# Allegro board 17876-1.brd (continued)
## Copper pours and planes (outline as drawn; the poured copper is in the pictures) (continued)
GND on BOTTOM: 66.36,27.43 65.09,28.7 65.09,34.81 65.3,35.03 66.29,35.03 66.52,34.8 70.98,34.8 72.89,32.89 72.89,31.26 73.75,30.39 73.75,27.84 73.72,27.81 71.41,27.81 71.03,27.43 ; 3 cut-outs
GND on BOTTOM: 19.81,75.62 18.75,76.68 18.14,76.68 17.93,76.89 17.93,78.21 18.75,79.03 18.76,79.02 21.54,79.02 21.72,78.84 21.72,75.8 21.54,75.62 ; 2 cut-outs
GND on BOTTOM: 72.03,39.93 71.77,40.18 71.63,40.18 71.55,40.26 71.55,40.54 72,40.99 72,41.62 72.15,41.78 72.4,41.78 72.61,41.56 74.16,41.56 74.27,41.68 74.27,42.13 74.07,42.33 73.86,42.33 73.52,42.67 73.19,42.67 72.44,43.43 72.44,45 72.46,45.02 72.88,45.02 73.02,44.88 73.02,44.68 74.39,43.32 74.59,43.32 75.2,42.71 75.2,42.65 74.73,42.17 74.73,41.73 75.51,40.95 75.83,40.95 75.93,40.84 76.33,40.84 76.43,40.95 76.83,40.95 76.94,40.84 77.14,40.84 77.24,40.95 77.98,40.95 78.11,40.82 79.55,40.82 79.58,40.84 79.58,41.43 79.15,41.86 79.15,41.96 79.32,42.14 79.38,42.14 80.31,43.08 80.31,43.28 79.73,43.87 79.73,44.12 79.86,44.25 80.14,44.25 80.7,43.69 80.7,42.57 80.14,42.01 80.14,41.86 80.29,41.71 80.29,40.92 80.42,40.79 81.74,40.79 82.02,41.07 82.37,41.07 82.85,40.59 82.85,40.29 82.83,40.26 79.2,40.26 79.07,40.39 78.64,40.39 78.54,40.29 78.13,40.29 78.03,40.39 77.47,40.39 77.33,40.25 75.74,40.25 75.66,40.33 73.25,40.33 72.91,39.99 72.56,39.99 72.5,39.93
GND on BOTTOM: 98.7,90.32 97.61,91.42 97.61,92.58 97.92,92.89 101.85,92.89 102.13,92.61 102.13,90.65 101.8,90.32 ; 4 cut-outs
GND on L2VCC: outline of 118 points within 0.51,0.51 178.39,102.49 ; 2 cut-outs
GND on L3: outline of 131 points within 0.51,0.51 178.39,102.49 ; 2 cut-outs
GND on L4: outline of 126 points within 0.51,0.51 178.39,102.49 ; 2 cut-outs
GND on L5GND: outline of 118 points within 0.51,0.51 178.39,102.49 ; 1 cut-out
VDDCR_FCH on TOP: 68.76,57.66 68.71,57.71 68.71,59.49 66.85,59.49 65.99,60.35 64.92,60.35 64.67,60.1 64.01,60.1 63.8,59.89 62.76,59.89 62.64,60.02 61.21,60.02 59.94,61.29 59.94,62.69 59.95,62.69 59.95,63.18 60.15,63.38 66.39,63.38 69.06,60.71 70.38,60.71 70.9,60.19 71.64,60.19 71.78,60.05 71.78,58.88 71.2,58.29 70.31,58.29 69.67,57.66
VDDCR_FCH on BOTTOM: 60.81,60.45 60.6,60.66 60.1,60.66 59.39,61.37 59.39,66.24 59.49,66.35 60.3,66.35 60.83,65.81 60.83,62.21 61.47,61.57 61.47,60.58 61.34,60.45 ; 4 cut-outs
VDDCR_FCH on BOTTOM: 70.11,57.74 69.86,57.99 69.86,58.37 70.49,59.01 71.76,59.01 72.02,58.76 72.02,58.37 72.14,58.25 72.14,57.87 72.02,57.74
VDDCR_FCH on L3: 71.81,60.17 71.81,58.57 71.53,58.29 70.28,58.29 70.18,58.4 70.18,58.85 70.04,58.99 66.76,58.99 65.56,60.2 64.95,60.2 64.68,59.93 63.86,59.93 63.67,59.74 61.24,59.74 60.1,60.89 60.1,62.56 60.63,63.1 61.52,63.1 62.1,62.51 63.86,62.51 64.97,61.39 70.59,61.39
0D6V_VREF_S0 on BOTTOM: 131.65,85.14 131.27,85.52 131.27,86.06 131.06,86.26 129.26,86.26 129.24,86.29 129.24,86.46 129.29,86.51 131.11,86.51 131.37,86.77 131.37,87 131.44,87.07 132.77,87.07 132.92,86.92 132.92,86.06 132,85.14 ; 1 cut-out
0D6V_VREF_S0 on BOTTOM: 140.21,38.99 140.13,39.07 140.13,40.36 140.23,40.46 141.66,40.46 141.78,40.34 141.78,39.14 141.63,38.99
0D95V_S0 on TOP: 41.78,90.12 41.66,90.25 41.66,90.88 41.78,91.01 42.93,91.01 43.31,91.39 43.56,91.39 43.69,91.26 43.69,90.76 43.05,90.12
0D95V_S0 on TOP: 80.79,53.6 80.62,53.77 80.62,55.63 80.44,55.63 80.26,55.81 80.26,57.15 79.68,57.74 79.68,59.46 79.38,59.77 79.38,61.6 79.6,61.83 79.6,63.45 79.15,63.91 79.15,64.59 78.33,65.41 78.33,66.68 74.4,70.61 74.4,78.74 74.52,78.87 75.16,78.87 75.92,79.63 77.24,79.63 77.69,79.19 77.69,78.55 79.15,77.09 81.51,77.09 84.87,73.73 84.87,60.09 85.12,59.84 85.12,57.84 85.39,57.56 85.39,56.11 84.73,55.45 84.73,54.66 84.68,54.61 82.51,54.61 82,54.1 81.53,54.1 81.03,53.6 ; 17 cut-outs
0D95V_S0 on BOTTOM: 75.78,75.81 75.62,75.97 75.62,79.81 75.59,79.83 77.11,79.83 77.44,79.5 78.51,79.5 78.56,79.45 78.56,76.63 77.74,75.81 ; 3 cut-outs
0D95V_S0 on BOTTOM: 80.72,53.46 80.08,54.09 79.25,54.09 79.13,54.22 79.13,54.56 79.73,55.17 79.73,55.52 79.63,55.63 79.63,56.72 79.65,56.74 79.65,58.69 80.19,59.23 81.8,59.23 82.48,58.55 82.48,58.19 81.6,57.3 81.6,56.57 81.69,56.48 82.33,56.48 82.83,55.98 83.38,55.98 83.57,55.79 83.57,54.91 83.06,54.4 83.04,54.4 83.04,54.17 82.84,53.97 82.14,53.97 81.99,54.12 81.67,54.12 81.01,53.46
0D95V_S0 on L2VCC: 84.34,56.24 84.34,51.87 83.94,51.47 79.67,51.47 79.41,51.74 79.41,52.48 78.54,53.36 78.54,74.21 76.6,76.15 76.6,79.77 78.27,81.44 78.27,82.68 77.65,83.31 64.72,83.31 60.81,79.39 57.74,79.39 56.85,80.28 54.69,80.28 52.91,82.06 48.21,82.06 43.62,86.64 43.62,89.44 43,90.06 41.73,90.06 41.59,90.2 41.59,90.93 41.73,91.07 42.88,91.07 43.26,91.45 43.48,91.45 44.64,90.3 44.64,87.11 48.62,83.13 53.34,83.13 54.6,81.86 59.49,81.86 59.92,82.29 60.63,82.29 62.8,84.45 78.47,84.45 86.83,76.09 86.83,65.92 86.31,65.39 86.31,60.47 85.84,60 85.84,58.27 86.11,58.01
0D95V_S0 on L3: 82.64,51.41 79.98,51.41 79.38,52.01 79.38,52.99 78.59,53.79 78.59,54.1 80.77,56.29 80.77,58.52 80.95,58.7 82.19,58.7 82.4,58.5 82.4,57.15 82.62,56.93 83.03,56.93 84.26,55.7 84.26,53.03
0D95V_S0 on L4: 79.71,64.82 80.29,64.24 81.15,64.24 81.38,64.01 81.38,63.25 83.24,61.39 84.48,61.39 85.14,60.73 85.14,55.58 82.68,53.11 79.55,53.11 79.3,53.37 79.3,59.16 79.38,59.23 79.38,60.17 78.23,61.32 78.23,64.19 78.83,64.78 78.83,65.37 79.1,65.64 79.35,65.64 79.71,65.28
0D95V_S5 on TOP: 50.42,72.44 50.19,72.67 50.19,76.35 50.32,76.48 51.61,76.48 52.63,75.47 52.63,74.37 52.61,74.36 52.61,73.47 51.59,72.44
0D95V_S5 on TOP: 74.95,52.5 74.88,52.57 74.88,53.34 74.14,54.08 73.57,54.08 73.27,54.38 72.72,54.38 72.64,54.46 72.64,55.04 72.7,55.1 74.97,55.1 75.35,54.71 75.82,54.71 75.93,54.6 75.93,54.15 75.79,54.01 75.61,54.01 75.49,53.89 75.49,52.53 75.46,52.5 ; 1 cut-out
0D95V_S5 on BOTTOM: 74.04,80.01 73.79,80.27 73.79,83.09 74.12,83.42 77.34,83.42 77.8,82.96 78.46,82.96 78.64,82.78 78.64,81.05 78.46,80.88 77.93,80.88 77.74,80.68 77.74,80.43 77.32,80.01
0D95V_S5 on BOTTOM: 50.42,72.44 50.19,72.67 50.19,76.35 50.32,76.48 51.61,76.48 52.63,75.47 52.63,74.37 52.12,73.86 52.12,72.98 51.59,72.44
0D95V_S5 on L2VCC: 78.16,53.73 77.88,53.46 75.09,53.46 74.64,53.9 74.64,65.36 74.21,65.79 74.21,70.51 71.38,73.34 66.22,73.34 64.01,71.13 52.53,71.13 50.61,73.05 50.61,76.2 50.75,76.34 60.68,76.34 61.15,76.81 61.15,79.19 64.88,82.93 77.49,82.93 77.89,82.52 77.89,81.59 76.22,79.92 76.22,75.99 78.16,74.05
0D95V_S5 on L3: 50.55,73.1 51.31,72.34 57.1,72.34 57.35,72.09 59.13,72.09 59.41,72.37 61.29,72.37 66.78,77.85 70.79,77.85 73.91,80.98 75.95,80.98 76.96,81.99 76.96,84.15 76.45,84.66 61.26,84.66 59.45,82.84 56.86,82.84 56.36,82.35 56.36,80.6 57.63,79.33 57.63,78.56 56.95,77.88 55.85,77.88 55.83,77.85 55.47,77.85 54.74,77.12 52.04,77.12 50.55,75.62
1D2V_CPU_VDDNB on TOP: 83.62,51.56 82.97,52.21 82.75,52.21 82.62,52.34 82.62,53.42 82.69,53.49 83.31,53.49 83.52,53.29 83.52,52.88 83.51,52.87 83.51,52.65 83.99,52.17 83.99,51.74 83.81,51.56
1D2V_CPU_VDDNB on TOP: outline of 85 points within 70.51,40.08 81.16,53.36 ; 27 cut-outs
1D2V_CPU_VDDNB on BOTTOM: 47.5,55.83 47.24,56.08 47.24,57.23 47.12,57.35 47.12,60.4 47.62,60.91 47.62,62.05 47.75,62.18 48.82,62.18 49.15,62.51 49.15,63.37 49.61,63.83 53.21,63.83 55.68,66.3 57.33,66.3 57.38,66.24 57.38,65.28 57.15,65.05 57.15,63.04 56.92,62.82 55.45,62.82 54.86,62.23 54.86,56.08 54.61,55.83 ; 6 cut-outs
1D2V_CPU_VDDNB on BOTTOM: outline of 145 points within 71.49,41.18 84.7,53.01
1D2V_CPU_VDDNB on L2VCC: 76.16,43.84 76.16,42.5 75.44,41.77 73.69,41.77 73.21,42.25 64.26,42.25 51.68,54.84 51.68,55.4 51.31,55.77 48.54,55.77 47.71,56.6 47.71,62.14 49.48,62.14 52.86,65.52 73.94,65.52 74.26,65.2 74.26,53.75 74.93,53.08 78.28,53.08 79.03,52.32 79.03,47.55 78.07,46.59 78.07,45.9 77.82,45.66 77.44,45.66 77.13,45.34 77.13,44.81
1D2V_CPU_VDDNB on L3: 78.02,53.41 79.03,52.4 79.03,47.43 78.18,46.59 78.18,45.7 78.03,45.54 77.22,45.54 77.19,45.52 77.19,44.81 76.32,43.94 76.32,42.39 75.61,41.68 73.69,41.68 73.1,42.26 69.31,42.26 69.09,42.04 64.47,42.04 50.81,55.71 50.81,55.71 48.56,55.71 47.8,56.47 47.8,63.02 48.67,63.88 58.72,63.88 58.9,63.7 58.9,61.85 65.71,55.04 65.91,55.04 65.91,54.94 66.92,53.94 68.52,53.94 69.67,52.78 72.47,52.78 73.09,53.41
1D2V_CPU_VDDNB on L4: 83.74,52.96 84.3,52.4 84.3,51.26 84.12,51.08 79.65,51.08 78.99,50.42 78.99,47.37 78.18,46.56 78.18,45.85 77.93,45.59 77.24,45.59 77.19,45.54 77.19,44.83 76.52,44.16 76.19,44.16 75.92,44.43 75.36,44.43 73.18,42.24 71.96,42.24 71.91,42.29 70.92,42.29 70.43,42.78 70.43,45.75 71.37,46.69 71.37,47.17 69.82,48.72 69.82,51.23 71.55,52.96
1D2V_S3 on TOP: 86.73,42.98 86.22,43.48 86.22,44.52 85.61,45.14 85.61,48.1 86.95,49.45 86.95,49.91 86.72,50.14 86.72,50.81 86.85,50.94 86.85,51.72 86.97,51.84 86.97,52.83 86.7,53.1 85.43,53.1 84.73,53.8 84.73,54.43 87.19,54.43 87.29,54.54 87.29,56.23 86.83,56.69 86.74,56.69 86.03,57.41 86.03,59.16 86.2,59.33 87.45,59.33 88.2,60.08 88.2,60.29 88.13,60.36 87.48,60.36 87.4,60.44 87.4,61.55 87.55,61.7 88.06,61.7 88.37,61.39 88.37,61.11 88.52,60.96 93.14,60.96 94.97,59.13 94.97,58.55 95.3,58.22 95.3,53.85 96.98,52.17 96.98,43.56 96.39,42.98 ; 19 cut-outs
1D2V_S3 on TOP: 125.15,45.92 124.26,46.81 123.06,46.81 122.05,47.83 122.05,50.75 122.17,50.88 122.17,55.32 122.68,55.32 122.81,55.45 122.81,56.34 122.68,56.47 122.3,56.47 121.93,56.83 121.93,61.28 121.16,62.05 121.16,62.69 121.28,62.82 127,62.82 127,62.31 127.25,62.05 133.6,62.05 133.73,61.93 133.73,50.29 132.72,49.28 132.72,48.08 131.44,46.81 128.17,46.81 127.28,45.92 ; 28 cut-outs
1D2V_S3 on L2VCC: 123.72,45.48 115.59,37.35 97.81,37.35 96.87,36.41 91.01,36.41 89.6,37.83 89.6,41.08 88.22,42.46 86.54,42.46 86.4,42.6 86.4,44.99 85.69,45.7 85.69,50.4 84.72,51.36 84.72,56.08 86.57,57.93 86.95,57.93 90.38,61.36 92.92,61.36 94.07,62.51 115.46,66.26 125.19,66.26 125.65,65.8 127.03,65.8 127.87,66.64 129.11,66.64 132.35,63.4 132.35,47.93 131.24,46.83 128.17,46.83 126.83,45.48
1D8V_AUX_PWR on BOTTOM: 69.47,21.67 69.19,21.95 68.61,21.95 68.43,22.13 68.43,23.55 68.45,23.57 69.8,23.57 70.23,23.14 70.23,21.72 70.18,21.67 ; 1 cut-out
1D8V_AUX_S5 on TOP: 50.12,23.37 50.01,23.48 50.01,24.29 49.68,24.61 49.68,25.68 49.76,25.76 50.16,25.76 50.27,25.66 50.27,25.22 50.8,24.69 50.8,23.52 50.65,23.37 ; 1 cut-out
1D8V_PWR on BOTTOM: 98.5,93.4 98.4,93.5 98.4,94.44 98.53,94.57 99.47,94.57 99.52,94.62 99.52,99.42 99.57,99.47 100.66,99.47 101.3,98.83 101.3,98.33 102.62,97 102.62,94.72 103.17,94.16 103.17,93.52 103.05,93.4 ; 6 cut-outs
1D8V_PWR_VIN on BOTTOM: 68.53,23.7 68.35,23.88 68.35,25.88 68.36,25.89 68.36,26.18 68.54,26.36 70.02,26.36 70.21,26.17 70.21,23.78 70.13,23.7 ; 3 cut-outs
1D8V_S0 on BOTTOM: 76.86,74.17 76.68,74.35 76.68,75.52 76.76,75.59 77.98,75.59 80.19,77.8 80.19,78.61 79.91,78.89 79.91,79.4 79.98,79.48 81,79.48 81.25,79.73 82.37,79.73 83.08,80.44 83.08,81.03 83.01,81.1 83.01,83.06 83.03,83.06 83.03,84.18 83.16,84.3 83.79,84.3 84.07,84.02 84.07,83.06 84.15,82.98 84.15,79.12 84.12,79.12 83.85,78.84 83.13,78.84 82.5,78.21 82.5,77.17 79.96,74.63 78,74.63 77.55,74.17 ; 4 cut-outs
1D8V_S0 on BOTTOM: 78.26,17.34 78.04,17.57 78.04,18.98 76.56,20.45 76.56,22.16 76.18,22.54 74.46,22.54 74.24,22.77 74.24,25.99 75.48,27.23 78.61,27.23 79.02,26.82 79.53,26.82 79.65,26.95 79.65,27.84 77.8,29.69 77.8,29.71 77.58,29.92 77.58,31.37 77.62,31.41 77.99,31.41 78.08,31.32 86.23,31.32 86.77,30.79 86.77,26.57 87.25,26.09 87.83,26.09 87.99,25.94 87.99,23.95 87.96,23.93 87.53,23.93 87.5,23.95 87.5,24.79 87.35,24.94 86.86,24.94 86.85,24.95 86.3,24.95 85.84,25.41 85.84,26.42 85.39,26.86 85.39,28.5 85.22,28.68 80.95,28.68 80.39,28.12 80.39,26.77 79.83,26.21 79.2,26.21 78.94,26.47 75.72,26.47 75.2,25.95 74.8,25.95 74.59,25.75 74.59,23.15 74.74,23.01 75.35,23.01 75.44,23.09 75.44,23.22 75.42,23.23 75.53,23.34 76.82,23.34 77.4,22.76 77.4,20.96 79.02,19.34 79.02,17.47 78.89,17.34 ; 6 cut-outs
1D8V_S0 on L3: 76.26,68.01 75.91,67.66 75.91,64.26 76.4,63.77 76.4,62.61 76.43,62.59 76.43,61.41 77.38,60.46 77.38,59 76.96,58.58 76.96,56.21 76.48,55.73 76.48,54.98 76.81,54.64 77.46,54.64 77.59,54.77 77.59,55.14 79.48,57.02 79.48,62.66 78.34,63.8 78.34,68.65 78.97,69.29 78.97,70.77 80.07,71.87 80.07,74.21 82.8,76.94 82.8,78.67 82.65,78.82 80.64,78.82 79.25,77.42 79.25,76.79 75.56,73.1 75.56,70.64 76.25,69.95 76.25,68.73 76.26,68.72
1D8V_S5 on TOP: 75.56,55.63 75.49,55.7 75.49,57.1 75.69,57.3 75.69,57.81 76.02,58.14 76.02,59.34 76.05,59.36 76.94,59.36 77.06,59.23 77.06,57.28 76.99,57.2 76.45,57.2 76.3,57.05 76.3,55.78 76.15,55.63 ; 3 cut-outs
1D8V_S5 on BOTTOM: 61.67,32.29 60.86,33.1 59.84,33.1 59.69,33.25 59.69,33.81 59.77,33.89 60.22,33.89 60.4,33.71 61.32,33.71 61.98,33.05 63.3,33.05 63.42,33.17 63.42,33.63 63.55,33.76 64.11,33.76 64.39,34.04 64.74,34.04 64.85,33.94 64.85,33.28 63.86,32.29 ; 2 cut-outs
1D8V_S5 on BOTTOM: 79.98,80.9 79.98,82.07 80.42,82.5 80.42,83.16 80.87,83.62 80.87,87.35 80.62,87.61 80.62,92.71 81.71,93.8 91.31,93.8 91.72,93.4 93.01,93.4 98.17,98.55 99.36,98.55 99.44,98.48 99.44,96.17 99.36,96.09 98.73,96.09 98.42,95.79 98.42,95.4 94.46,91.44 83.21,91.44 82.4,90.63 82.4,90.35 82.68,90.07 82.68,84.76 82.91,84.53 82.91,82.07 81.97,81.13 81.31,81.13 81.29,81.14 81.05,80.9
1D8V_S5 on L3: 76.15,55.58 75.46,55.58 75.3,55.74 75.3,57.24 74.57,57.96 74.57,58.65 73.91,59.31 73.91,59.34 73.36,59.89 73.36,59.92 73.18,60.1 73.18,61.62 72.95,61.85 72.95,71.88 73.19,72.13 73.19,79.62 73.91,80.34 75.44,80.34 75.53,80.43 76.49,80.43 78.49,82.42 78.51,82.42 78.97,82.88 83.59,82.88 85.01,81.46 85.01,80.39 83.83,79.21 79.35,79.21 78.87,78.73 78.87,76.79 74.96,72.87 74.96,69.06 75.64,68.38 75.64,61.72 77.22,60.15 77.22,59.03 76.85,58.66 76.85,58.54 76.83,58.52 76.83,56.26
1D8V_SPI_S5 on BOTTOM: 76.83,25.1 76.73,25.2 76.73,26.29 76.81,26.37 78.87,26.37 79.22,26.01 79.22,25.12 79.2,25.1
1D8V_SPI_S5 on BOTTOM: 79.02,15.06 78.24,15.84 77.61,15.84 77.09,16.36 75.31,16.36 75.18,16.49 75.18,17.17 75.46,17.45 75.46,18.16 75.54,18.24 76.48,18.24 76.82,18.58 76.82,19.28 76.4,19.7 75.23,19.7 74.99,19.93 74.99,20.52 75.41,20.93 75.41,22.26 75.5,22.36 75.92,22.36 76.22,22.06 76.22,20.67 77.89,19 77.89,17.44 78.32,17.01 78.67,17.01 78.67,17.01 78.94,17.01 78.95,17.02 79.04,17.02 79.16,17.14 79.16,17.64 79.33,17.81 79.55,17.81 79.81,17.55 79.81,17.19 79.68,17.07 79.68,15.11 79.63,15.06
3D3V_AUX_KBC on BOTTOM: 71.63,22.96 71.45,23.14 71.45,23.75 71.55,23.85 72.11,23.85 72.31,24.06 72.31,25.2 72.19,25.33 72.19,26.57 72.39,26.77 72.85,26.77 73.09,26.53 73.09,25.8 73.41,25.48 73.41,23.06 73.3,22.96
3D3V_AUX_S5 on TOP: 40.67,22.2 40.54,22.33 40.54,22.94 40.39,23.09 39.7,23.09 39.65,23.14 39.65,23.52 39.78,23.65 41.43,23.65 41.61,23.47 41.61,22.53 41.27,22.2 ; 1 cut-out
3D3V_AUX_S5 on L4: 41.26,22.25 42.8,22.25 43.81,23.27 44.78,23.27 44.88,23.17 46.79,23.17 47.02,23.4 47.02,23.9 46.86,24.06 43.08,24.06 42.24,23.22 41.46,23.22 41.21,22.96 41.2,22.96 41.11,22.87 41.11,22.4
3D3V_CAMERA_S0 on BOTTOM: 68.48,80.32 68.4,80.39 68.4,82.91 68.55,83.06 68.55,83.95 68.12,84.38 67.44,84.38 67.02,84.8 66.66,84.8 66.65,84.81 65.46,84.81 65.46,85.93 65.53,86.01 67.94,86.01 69.67,84.28 69.67,81.79 70.15,81.31 70.15,80.42 70.05,80.32 ; 4 cut-outs
3D3V_CARD on TOP: 15.88,26.62 15.77,26.72 15.77,30.74 15.95,30.91 16.43,30.91 16.61,30.74 16.61,26.67 16.56,26.62
3D3V_CARD on BOTTOM: 6.4,36.78 6.25,36.93 6.25,37.62 6.48,37.85 9.14,37.85 9.3,37.7 10.91,37.7 11.03,37.81 11.03,38.59 11.04,38.59 11.33,38.59 11.34,38.59 11.34,37.73 10.72,37.11 9.86,37.11 9.58,36.83 8.28,36.83 8.23,36.78 ; 3 cut-outs
3D3V_CARD on BOTTOM: 15.93,25.45 15.6,25.78 14.2,25.78 14.17,25.78 14.15,25.8 14.15,26.42 14.17,26.44 15.44,26.44 15.8,26.8 15.8,28.09 16.03,28.32 16.54,28.32 17.18,27.68 17.18,25.52 17.12,25.45 ; 1 cut-out
3D3V_CARD_S0 on BOTTOM: 9.43,35.81 9.35,35.89 9.35,36.5 9.49,36.64 9.63,36.64 9.94,36.96 10.79,36.96 11.56,37.72 11.56,38.61 11.81,38.61 11.86,38.56 11.86,37.31 11.98,37.2 11.98,36.35 11.71,36.08 11.1,36.08 10.83,35.81 ; 2 cut-outs
3D3V_LCDVDD_S0 on BOTTOM: 61.77,80.16 61.65,80.29 61.65,82.25 61.65,82.25 61.65,82.5 61.76,82.61 63.32,82.61 63.7,83 63.7,84.46 63.95,84.7 63.95,85.63 63.96,85.65 64.72,85.65 64.74,85.63 64.74,84.18 65.38,83.54 65.38,81.48 65.1,81.21 62.81,81.21 62.76,81.15 62.76,80.29 62.64,80.16 ; 4 cut-outs
3D3V_MSATA_S0 on BOTTOM: 145.06,30.41 144.96,30.51 144.96,33.61 143.48,35.08 143.23,35.08 143,35.31 143,36.2 143.13,36.32 149.61,36.32 150.5,35.43 150.5,31.19 150.27,30.96 147.22,30.96 146.66,30.41 ; 3 cut-outs
3D3V_S0 on TOP: 151.22,84.34 150.09,85.47 150.09,85.85 150.15,85.92 151.6,85.92 152.1,85.42 152.1,84.52 151.92,84.34 ; 1 cut-out
3D3V_S0 on TOP: 107.47,1.33 107.21,1.59 107.21,3.45 107.6,3.85 131.57,3.85 140.23,12.5 141.66,12.5 145.69,16.54 145.69,19.59 146.25,20.14 146.25,39.5 147.24,40.49 147.24,41.3 147.52,41.58 147.52,45.09 146.86,45.75 146.86,47.8 146.46,48.21 146.46,50.67 146.86,51.08 146.86,60.05 143.43,63.48 143.43,65.74 143.38,65.79 143.38,70.31 147.19,74.12 149.48,74.12 149.61,73.99 149.61,72.33 149.35,72.07 147.94,72.07 145.41,69.55 145.41,65.36 148.34,62.43 149.89,62.43 151.21,61.11 151.21,51.44 150.5,50.73 149.43,50.73 148.46,49.76 148.46,49.28 149.53,48.21 150.52,48.21 151.36,47.37 151.36,14.58 150.19,13.41 148.76,13.41 144.65,9.3 141.64,9.3 136.45,4.11 136.45,3.63 136.19,3.38 135.72,3.38 133.66,1.33 ; 5 cut-outs
3D3V_S0 on TOP: 38.63,27.15 38.38,27.41 38.38,27.48 38.13,27.74 37.31,27.74 36.55,28.5 36.55,29.47 36.12,29.9 34.52,29.9 28.65,35.76 28.65,36.55 28.98,36.88 29.57,36.88 29.95,36.5 29.95,35.66 34.72,30.89 37.41,30.89 39.47,28.83 39.47,28.55 40.17,27.86 40.17,27.35 40.05,27.24 39.54,27.24 39.52,27.26 39.42,27.15 ; 1 cut-out
3D3V_S0 on TOP: 15.54,32.92 15.44,33.02 15.44,33.76 14.3,34.9 8.61,34.9 8.57,34.86 7.49,35.94 7.49,36.39 7.7,36.6 14.59,36.6 15.74,35.46 16.1,35.46 16.43,35.13 16.43,33 16.36,32.92
3D3V_S0 on TOP: outline of 104 points within 52.22,21.11 109.33,99.06 ; 9 cut-outs
3D3V_S0 on TOP: 78.97,54.07 78.55,54.49 78.55,54.98 78.18,55.35 78.18,56.42 78.46,56.7 79.12,56.7 79.27,56.55 79.27,55.6 79.32,55.55 79.66,55.55 79.74,55.48 79.74,54.19 79.61,54.07 ; 1 cut-out
3D3V_S0 on BOTTOM: 90.5,86.59 90.47,86.62 90.47,87.71 90.78,88.01 90.78,88.42 90.83,88.47 91.36,88.47 91.54,88.29 91.9,88.29 92.23,88.62 93.68,88.62 94.21,88.09 94.56,88.09 94.69,87.96 94.69,87.56 94.56,87.43 93.83,87.43 93.27,87.99 92.61,87.99 91.21,86.59 ; 1 cut-out
3D3V_S0 on BOTTOM: 150.75,53.9 149.86,54.79 148.54,54.79 148.54,55.07 148.56,55.09 149.48,55.09 149.68,55.3 149.68,56.64 149.69,56.66 149.69,56.91 149.78,57 150.29,57 150.34,56.95 150.34,55.42 150.98,54.79 151.41,54.79 151.43,54.76 151.43,54.03 151.31,53.9
3D3V_S0 on BOTTOM: 15.48,32.79 15.29,32.97 15.29,33.86 15.42,33.99 16.93,33.99 19.95,37.01 24.8,37.01 25.77,36.03 28.64,36.03 28.75,36.15 28.75,36.6 28.87,36.72 28.87,36.87 28.93,36.93 29.44,36.93 29.6,36.77 29.6,36.59 29.62,36.58 29.62,35.69 29.05,35.12 24.58,35.12 23.76,35.94 20.75,35.94 17.59,32.79
3D3V_S0 on BOTTOM: 144.96,55.3 144.93,55.32 144.93,55.6 144.09,56.44 143.33,56.44 143.21,56.57 143.21,57.02 143.23,57.05 145.19,57.05 145.87,56.36 145.87,55.3 ; 1 cut-out
3D3V_S0 on BOTTOM: 107.57,1.25 107.31,1.5 107.31,2.47 105.08,4.7 74.22,4.7 71.88,7.04 53.95,7.04 50.56,10.43 50.56,14.18 50.71,14.33 54.13,14.33 58.38,10.07 60.54,10.07 60.55,10.06 73.22,10.06 76.23,7.05 108.52,7.05 110.59,4.98 110.59,1.25
3D3V_S0 on BOTTOM: 88.38,13.68 88.19,13.87 88.19,14.63 88.09,14.73 87.53,14.73 87.38,14.89 87.38,15.98 87.5,16.11 88.21,16.11 88.46,15.86 88.79,15.86 88.8,15.88 89.94,15.88 89.99,15.83 89.99,15.57 89.94,15.52 88.9,15.52 88.7,15.32 88.7,14.63 88.82,14.51 91.64,14.51 91.87,14.73 91.87,15.37 91.74,15.5 90.65,15.5 90.6,15.55 90.6,15.88 90.63,15.9 91.67,15.9 91.85,16.08 92.35,16.08 92.48,16.21 92.48,17.73 93.55,18.8 94.92,18.8 95.99,19.86 95.99,21.08 96.65,21.74 96.65,24.92 94.84,26.72 92.43,26.72 92.28,26.57 92.28,25.76 91.52,25 91.52,23.32 91.49,23.29 90.68,23.29 90.54,23.43 90.54,26.43 92.72,28.61 93.43,28.61 93.51,28.52 93.51,27.85 93.72,27.64 95.17,27.64 99.9,22.91 99.9,21.29 99.35,20.74 96.91,20.74 96.6,20.42 96.6,19.2 95.38,17.98 93.68,17.98 93.01,17.32 93.01,14 92.7,13.68 ; 5 cut-outs
3D3V_S0 on BOTTOM: 143.21,36.73 142.98,36.96 142.98,37.75 143.56,38.33 143.56,41.07 143.87,41.38 144.3,41.38 144.7,40.97 147.19,40.97 147.49,41.26 147.66,41.26 148.74,40.18 148.74,37.47 148.79,37.42 148.79,37.24 148.29,36.73 ; 2 cut-outs
3D3V_S0 on BOTTOM: 60.6,76.63 60.55,76.68 60.55,77.19 60.66,77.29 60.96,77.29 61.84,78.17 61.84,78.48 61.98,78.61 63.44,78.61 63.7,78.35 63.7,77.26 63.51,77.06 62.98,77.06 62.52,77.52 62.15,77.52 61.9,77.27 61.9,77.04 61.49,76.63
3D3V_S0 on BOTTOM: 148.29,71.99 148.11,72.16 148.11,75.03 148.13,75.06 149,75.06 149.12,74.93 149.12,73.84 149.56,73.41 149.56,72.39 149.15,71.99
3D3V_S0 on BOTTOM: 38.46,27.21 38.35,27.31 38.35,27.66 38.25,27.76 37.74,27.76 37.59,27.61 37.08,27.61 37,27.7 37,28.79 36.63,29.16 36.63,30.08 37.01,30.46 38.56,30.46 38.72,30.29 38.72,30.06 38.91,29.87 39.32,29.87 39.45,29.75 39.45,28.53 39.78,28.2 39.78,28.02 38.96,27.21 ; 3 cut-outs
3D3V_S0 on BOTTOM: 67.69,78.31 67.51,78.49 67.51,79.5 67.77,79.76 70.13,79.76 70.46,80.09 71.55,80.09 71.6,80.04 71.6,78.56 71.35,78.31 ; 2 cut-outs
3D3V_S0 on L2VCC: 60.75,15.38 57.96,12.59 48.72,12.59 41.85,19.46 41.85,25.94 41.13,26.66 37.75,26.66 37.12,27.28 37.12,28.94 36.69,29.37 36.69,29.64 39.43,32.38 39.43,33.02 40.08,33.67 53.52,33.67 63,24.19 100.64,24.19 101.03,23.8 101.03,18.9 100.68,18.56 94.16,18.56 90.98,15.38
3D3V_S0 on L4: 150.88,85.93 150.88,84.65 151.09,84.43 152.2,84.43 152.21,84.44 152.4,84.24 152.4,77.93 151.32,76.85 150.18,76.85 147.96,74.63 147.96,71.71 148.34,71.32 150.88,71.32 151,71.45 151,74.25 151.38,74.63 152.65,74.63 154.56,76.53 154.56,84.66 153.16,86.06 151,86.06
3D3V_S5 on TOP: 41.71,16.44 41.53,16.61 41.53,18.11 41.61,18.19 42.7,18.19 42.8,18.09 42.8,16.92 42.32,16.44
3D3V_S5 on TOP: 134.24,68.02 132.84,69.42 132.84,77.42 132.63,77.64 132.63,90.59 131.44,91.77 128.91,91.77 127.76,92.91 119.63,92.91 118.24,94.31 112.27,94.31 112.01,94.57 112.01,96.32 112.55,96.85 118.77,96.85 120.93,94.69 131.44,94.69 135.89,90.25 135.89,80.09 136.4,79.58 136.65,79.58 136.65,79.02 136.55,78.92 135.31,78.92 134.11,77.73 134.11,69.8 134.63,69.28 137.4,69.28 137.91,69.79 139.59,69.79 139.7,69.68 139.7,69.04 139.19,68.53 138.3,68.53 137.92,68.15 137.92,68.13 137.91,68.13 137.8,68.02
3D3V_S5 on TOP: 69.95,73.2 69.75,73.41 69.75,74.04 70.08,74.37 71.65,74.37 72.09,74.8 72.09,79.99 73.19,81.09 76.03,81.09 77.14,82.2 81.03,82.2 82.17,81.05 82.17,80.27 84.25,78.18 86.06,78.18 87.88,80.01 99.09,80.01 104.21,85.13 104.21,86.15 103.81,86.55 103.81,87.97 104.4,88.56 105.18,88.56 105.93,87.81 105.93,84.52 99.67,78.26 90.12,78.26 88.7,76.84 83.95,76.84 80.21,80.57 80.21,80.67 78.08,80.67 77.22,79.81 73.66,79.81 73.38,79.53 73.38,74.09 72.49,73.2
3D3V_S5 on TOP: 50.93,11.33 50.41,11.84 50.41,12.1 47.14,15.37 47.1,15.37 47.1,18.82 47.75,19.48 47.97,19.48 48.1,19.61 48.1,20.08 48.13,20.11 48.62,20.11 48.78,19.95 48.78,18.07 48.11,17.4 48.11,17.14 48.36,16.89 48.36,16.34 48.38,16.31 48.38,15.07 50.96,12.49 51.6,12.49 51.98,12.11 52.3,12.11 52.43,11.99 52.43,11.49 52.26,11.33
3D3V_S5 on BOTTOM: 34.11,27.66 33.63,28.14 33.63,33.22 33.68,33.28 36.35,33.28 37.17,32.45 37.17,31.1 36.47,30.41 36.47,29.14 36.78,28.83 36.78,28.55 36.58,28.35 36.09,28.35 35.92,28.53 35.86,28.53 35.69,28.35 35.69,27.66 ; 2 cut-outs
3D3V_S5 on BOTTOM: 141,67.13 140.98,67.15 140.6,67.15 140.59,67.16 140.08,67.16 138.7,68.54 138.7,68.98 139.29,69.57 139.55,69.57 140.27,68.85 142.89,68.85 143.87,69.83 143.87,72.87 147.57,76.58 149.12,76.58 149.25,76.46 149.25,76.15 149.33,76.07 149.33,75.36 149.2,75.24 148.06,75.24 147.35,74.53 147.35,73.31 145.8,71.76 145.8,69.29 143.64,67.13 ; 1 cut-out
3D3V_S5 on BOTTOM: 111.73,22.18 111.12,22.79 111.12,24.16 111.89,24.92 111.89,78.69 103.83,86.75 103.83,88.8 107.82,92.79 110.24,92.79 111.46,94.01 111.46,97.16 111.15,97.46 110.52,97.46 110.24,97.74 110.24,98.33 110.31,98.4 112.19,98.4 112.5,98.1 112.5,96.78 112.62,96.65 113.87,96.65 114.22,96.29 114.22,93.42 110.94,90.14 108.6,90.14 107.57,89.1 107.57,86.84 109.09,85.31 109.09,85.29 114.81,79.58 114.81,22.56 114.43,22.18 ; 1 cut-out
3D3V_S5 on BOTTOM: 58.74,52.48 58.62,52.59 58.62,53.29 59.23,53.9 59.49,53.9 60.25,54.66 60.25,55.02 60.33,55.09 60.78,55.09 60.99,54.89 60.99,54.33 61.21,54.1 62.48,54.1 62.61,53.98 62.81,53.98 62.99,53.8 62.99,53.42 62.92,53.34 62.38,53.34 62.18,53.54 61.44,53.54 61.34,53.44 61.34,53.32 61.32,53.3 59.97,53.3 59.73,53.07 59.73,52.86 59.35,52.48 ; 2 cut-outs
3D3V_S5 on L2VCC: 113.02,22.06 111.38,22.06 108.87,24.57 63.15,24.57 53.67,34.05 39.93,34.05 39.05,33.18 39.05,32.54 36.31,29.8 36.31,29.21 36.74,28.78 36.74,28.28 36.12,28.28 32.04,32.36 32.04,33.07 36.88,37.91 51.17,37.91 52.02,38.77 53.58,38.77 57.28,35.06 62.55,35.06 62.98,34.63 62.98,34.15 62.98,34.15 62.98,33.99 62.98,33.99 62.98,31.87 67.37,27.48 111.01,27.48 113.6,24.89 113.6,22.64
3D3V_WLAN_S0 on TOP: 164.59,93.93 164.34,94.18 164.34,95.07 164.59,95.33 166.88,95.33 167.13,95.07 167.13,94.06 167,93.93 ; 3 cut-outs
3D3V_WLAN_S0 on BOTTOM: 160.15,93.93 160.15,94.82 160.66,95.33 167,95.33 167.26,95.07 167.26,94.08 167.11,93.93
3D3V_WLAN_S0 on BOTTOM: 150.62,73.48 150.44,73.66 149.73,73.66 149.4,73.99 149.4,75.11 149.43,75.13 149.43,76.07 150.44,76.07 151.13,75.39 152.02,75.39 152.4,75.01 152.4,73.99 151.89,73.48 ; 5 cut-outs
3D3V_WLAN_S0 on BOTTOM: 159.13,76.28 158.75,76.66 158.75,77.17 159.13,77.55 159.64,77.55 160.02,77.17 161.67,77.17 161.8,77.04 161.8,76.4 161.67,76.28
3D3V_WLAN_S0 on L3: 150.18,73.93 150.62,73.48 151.89,73.48 154.81,76.4 162.43,76.4 164.72,78.69 164.72,92.03 167,94.31 167,94.95 166.75,95.2 163.19,95.2 161.23,93.23 161.23,80.53 159.26,78.56 152.91,78.56 150.18,75.83
+DC_IN on TOP: 22.12,68.66 21.84,68.94 21.84,72.65 21.95,72.75 25.6,72.75 25.86,72.49 25.86,68.76 25.76,68.66 ; 10 cut-outs
+DC_IN on BOTTOM: 26.14,67.13 26.01,67.26 26.01,67.62 25.25,68.38 24.64,68.38 24.46,68.2 24.46,67.16 22.78,67.16 22.48,67.46 21.89,67.46 21.74,67.31 20.85,67.31 20.65,67.51 20.65,69.37 20.85,69.57 21.64,69.57 21.87,69.8 21.87,72.67 22,72.8 25.76,72.8 25.76,70.79 25.96,70.59 26.82,70.59 27.13,70.28 27.13,67.21 27.05,67.13 ; 4 cut-outs
+DC_IN_C on TOP: 22,72.98 21.84,73.13 21.84,74.88 23.24,76.28 23.24,77.12 24.36,78.23 26.37,78.23 26.54,78.06 26.54,73.18 26.34,72.98 ; 5 cut-outs
+DC_IN_C on BOTTOM: 21.97,72.98 21.86,73.09 21.86,74.58 23.29,76.01 24.12,76.01 24.26,76.15 24.26,77.93 24.52,78.2 26.3,78.2 26.52,77.97 26.52,73.15 26.34,72.98 ; 3 cut-outs
+SDC_IN on BOTTOM: 25.76,59.46 25.73,59.49 25.73,60.02 25.83,60.12 25.83,61.42 25.76,61.5 25.02,61.5 24.97,61.55 24.97,63.91 25.02,63.96 25.68,63.96 26.29,64.57 27.08,64.57 27.2,64.44 27.2,60.4 27.03,60.23 26.7,60.23 26.47,60 26.47,59.62 26.31,59.46
+VCHGR on BOTTOM: 129.59,5.06 129.59,9.02 129.68,9.11 131.05,9.11 131.24,9.3 131.24,11.84 134.57,11.84 135.64,12.9 139.7,12.9 139.83,12.78 139.83,10.24 136.91,7.32 136.91,6.05 135.92,5.06
AD+ on BOTTOM: 132.97,17.98 132.72,18.24 131.93,18.24 131.85,18.32 131.85,19.05 131.9,19.1 132.56,19.1 132.69,19.23 132.69,19.56 132.79,19.66 133.45,19.66 133.55,19.56 133.55,18.06 133.48,17.98 ; 1 cut-out
AD+ on BOTTOM: 21.54,59.34 21.39,59.49 21.39,60.12 21.06,60.45 21.06,65.28 20.75,65.58 20.75,66.98 20.88,67.11 21.87,67.11 22.07,67.31 22.33,67.31 22.83,66.8 25.63,66.8 25.63,64.16 25.58,64.11 24.77,64.11 24.66,64.01 24.66,60.33 24.61,60.28 23.01,60.28 22.94,60.2 22.94,59.46 22.81,59.34 ; 8 cut-outs
AUD_AGND on L2VCC: 144.32,84.34 143.98,84 143.98,83.16 143.55,82.73 143.55,82.17 142.91,81.54 142.91,81.18 142.85,81.12 141.91,81.12 141.02,80.23 139.59,80.23 139.33,80.49 139.33,81.46 138.95,81.84 138.95,84.05 138.64,84.37 138.25,84.37 137.22,85.4 137.22,90.45 136.21,91.47 136.21,92.99 134.05,95.15 134.05,98.3 134.42,98.67 137.36,98.67 138.12,97.91 141.76,97.91 142.75,98.9 150.72,98.9 150.91,98.7 150.91,97.94 151.56,97.3 152.7,97.3 153.23,96.77 153.23,95.52 151.67,93.41 150.42,93.41 149.65,92.65 144.32,92.65 143.62,91.95 143.62,90.17 143.6,90.15 142.25,90.15 141.08,88.98 141.08,86.77 140.23,85.92 140.23,84.8 140.53,84.51 141.16,84.51 141.5,84.85 141.5,85.1 141.95,85.55 142.89,85.55 143.21,85.87 143.21,86.53 143.59,86.91 143.59,88.08 143.83,88.32 144.97,88.32 145.06,88.23 145.06,87.09 144.22,86.25 144.22,85.38 144.44,85.17 144.44,85.11 144.72,84.83 144.72,84.36 144.7,84.34
AUD_AGND on L5GND: 143.7,91.98 143.7,88.8 140.65,85.75 140.65,84.41 140.33,84.09 139.65,84.09 139.38,84.36 139.38,85.34 139.89,85.85 139.89,90.96 139.46,91.4 136.54,91.4 136.23,91.71 136.23,92.86 135.73,93.36 135.21,93.36 134.3,94.26 134.3,95.53 133.29,96.55 133.29,98.04 133.94,98.69 137.34,98.69 138.1,97.93 141.68,97.93 142.57,98.82 150.04,98.82 151.56,97.3 152.19,97.3 152.34,97.15 152.34,95.66 151.81,95.14 150.67,95.14 149.91,94.38 148.13,94.38 147.64,93.88 147.64,92.99 147.37,92.72 144.45,92.72
AUD_SPK_11_L+ on BOTTOM: 89.48,98.38 89.38,98.48 89.38,99.52 92.41,99.52 92.48,99.6 92.48,100.64 92.56,100.71 93.52,100.71 93.65,100.59 93.65,99.21 92.81,98.38 ; 2 cut-outs
AUD_SPK_11_L- on BOTTOM: 89.41,99.72 89.41,100.74 89.43,100.76 92.2,100.76 92.23,100.74 92.23,99.87 92.08,99.72 ; 2 cut-outs
AUD_SPK_11_R+ on BOTTOM: 89.51,94.97 89.31,95.18 89.31,96.09 89.36,96.14 93.37,96.14 94.44,97.21 94.44,98.17 94.61,98.35 95.43,98.35 95.61,98.17 95.61,96.52 94.06,94.97 ; 2 cut-outs
AUD_SPK_11_R- on BOTTOM: 89.41,96.29 89.28,96.42 89.28,97.39 89.36,97.46 92.94,97.46 92.94,98.25 93.12,98.43 93.95,98.43 94.16,98.22 94.16,97.16 93.29,96.29 ; 2 cut-outs
AUD_SPK_L+_R on TOP: 148.62,77.24 148.46,77.4 148.46,78.49 148.51,78.54 149.48,78.54 149.71,78.77 151.18,78.77 151.23,78.72 151.23,77.83 150.72,77.32 150.72,77.32 150.64,77.24 ; 1 cut-out
AUD_SPK_L-_R on TOP: 148.53,78.83 148.41,78.94 148.41,79.99 148.49,80.06 151.1,80.06 151.21,79.96 151.21,79.02 151.1,78.92 149.3,78.92 149.21,78.83
AUD_SPK_R+_R on TOP: 148.46,81.61 148.34,81.74 148.34,82.5 148.83,82.99 151.49,82.99 151.59,82.9 151.59,81.66 151.54,81.61
AUD_SPK_R-_R on TOP: 148.46,80.34 148.34,80.47 148.34,81.23 148.59,81.48 151.49,81.48 151.54,81.43 151.54,80.44 151.43,80.34
DCBATOUT on TOP: outline of 123 points within 15.9,1.27 144.91,83.24 ; 26 cut-outs
DCBATOUT on BOTTOM: 38.1,80.44 37.82,80.72 37.82,83.26 38.53,83.97 40.94,83.97 41,83.92 41,80.49 40.94,80.44 ; 4 cut-outs
DCBATOUT on BOTTOM: 142.24,51.69 142.24,53.16 144.4,53.16 144.98,52.58 144.98,52.07 144.6,51.69
DCBATOUT on BOTTOM: 18.67,29.03 18.41,29.29 18.41,30.56 19.3,31.45 21.29,31.45 21.39,31.35 21.39,30.56 21.84,30.1 21.84,29.16 21.72,29.03 ; 1 cut-out
DCBATOUT on BOTTOM: 41.1,67.97 41.02,68.05 41.02,70.59 41.19,70.75 41.39,70.75 41.4,70.77 43.64,70.77 43.84,70.56 43.84,69.55 43.46,69.17 43.46,68.12 43.31,67.97 ; 1 cut-out
DCBATOUT on BOTTOM: 134.47,19.59 133.99,20.07 133.99,24.44 135.46,25.91 138.43,25.91 138.49,25.85 138.49,22.54 138.73,22.3 138.73,19.66 138.66,19.59
DCBATOUT on BOTTOM: 27.61,60.38 27.61,64.54 27.69,64.62 28.73,64.62 28.85,64.75 28.85,65.23 28.87,65.24 28.87,65.98 28.89,65.98 30.02,67.11 33.93,67.11 34.49,66.55 34.49,66.35 34.54,66.3 34.54,63.22 34.37,63.04 32.18,63.04 31.37,62.23 31.37,60.56 31.19,60.38 ; 4 cut-outs
DCBATOUT on BOTTOM: 18.72,10.9 18.16,11.46 17.22,11.46 17.02,11.66 17.02,13.24 17.02,13.24 17.1,13.32 17.94,13.32 18.06,13.44 21.21,13.44 21.49,13.16 21.84,13.16 21.86,13.17 22.36,13.17 22.5,13.03 22.5,11.38 22.02,10.9 ; 2 cut-outs
DCBATOUT on BOTTOM: 26.97,40.79 25.27,42.5 23.95,42.5 23.77,42.67 23.77,45.29 24.54,46.05 24.54,46.51 25.2,47.17 28.6,47.17 29.26,46.51 29.97,46.51 30.3,46.18 31.62,46.18 31.95,46.51 33.22,46.51 33.25,46.48 33.25,42.47 31.57,40.79
DCBATOUT on BOTTOM: 131.7,12.42 131.05,13.07 131.05,14.52 131.37,14.84 134.14,14.84 134.39,14.58 134.39,13.39 134.24,13.24 133.58,13.24 133.48,13.13 133.48,12.42
EC_AGND on BOTTOM: 47.07,34.14 47.07,35.71 46.89,35.89 46.89,36.96 45.82,38.03 45.82,39 45.89,39.07 46.65,39.07 46.72,38.99 46.71,38.98 46.71,37.92 46.93,37.71 47.33,37.71 47.47,37.57 47.47,36.22 47.68,36.02 47.68,35.79 47.62,35.74 47.55,35.74 47.24,35.43 47.24,34.14
EMMC_VCCQ on BOTTOM: 84.84,82.25 84.68,82.4 84.68,82.83 84.38,83.14 84.38,84.02 84.53,84.18 85.57,84.18 86.03,83.72 86.03,82.91 85.37,82.25 ; 2 cut-outs
HDMI_PLL_GND on TOP: 12.9,79.48 12.79,79.59 12.79,81.27 12.9,81.38 12.9,81.78 12.76,81.93 12.76,83.93 13.18,84.36 14.21,84.36 14.26,84.3 14.26,79.62 14.12,79.48
KBC_VCC on BOTTOM: 52.91,35.79 52.7,35.99 52.7,36.17 52.86,36.32 52.93,36.32 53.04,36.43 54.28,36.43 55.41,37.56 55.64,37.56 55.73,37.47 55.73,37.14 54.38,35.79
KBC_VCC on BOTTOM: 41.3,24.61 41.17,24.74 41.17,25.05 41.38,25.25 41.38,26.39 41.43,26.44 42.1,26.44 42.18,26.37 42.18,25.88 42.57,25.49 42.71,25.49 42.72,25.48 43.94,25.48 43.97,25.45 43.97,25.3 43.94,25.27 42.24,25.27 41.58,24.61
M_VREF_CA_DIMMA on TOP: 128.85,62.16 128.37,62.64 128.37,63.17 128.63,63.43 131.85,63.43 132.23,63.81 132.79,63.81 132.92,63.68 132.92,62.46 132.84,62.38 131.89,62.38 131.67,62.16 ; 5 cut-outs
MIC2_VREFO on TOP: 148.89,93.64 148.77,93.77 148.77,94.01 149.11,94.35 149.11,95.14 149.12,95.15 149.12,95.45 149.11,95.47 150.01,95.47 150.23,95.25 150.23,94.53 149.34,93.64
PWR_0D95V on TOP: 49,72.49 48.13,73.36 45.23,73.36 44.69,73.9 44.69,76.49 45.16,76.96 49.59,76.96 50.16,76.38 50.16,73.33 50.14,73.36 50.06,73.28 50.06,72.49
PWR_0D95V on BOTTOM: 44.04,71.45 43.99,71.5 43.99,73 43.71,73.28 42.75,73.28 41.53,74.5 41.53,78.06 41.66,78.18 44.2,78.18 44.58,77.8 49.81,77.8 49.91,77.7 49.91,71.68 49.68,71.45 ; 11 cut-outs
PWR_0D95V_BOOT on BOTTOM: 33.96,70 33.91,70.05 33.91,72.01 33.52,72.4 33.52,73.56 33.53,73.57 33.72,73.57 33.72,72.93 33.88,72.76 34.01,72.76 34.75,72.02 34.76,72.02 34.96,71.82 34.96,70.17 34.8,70
PWR_0D95V_PH on BOTTOM: 36.4,74.53 35.56,75.36 34.44,75.36 34.47,75.34 34.47,75.19 34.44,75.16 31.55,75.16 31.52,75.19 31.52,76.74 31.55,76.76 35.23,76.76 35.26,76.79 35.26,76.91 36.46,78.12 39.01,78.12 39.17,77.97 39.17,74.6 39.09,74.53
PWR_0D95V_PH on BOTTOM: 35.21,71.87 35.16,71.92 35.16,72.18 34.3,73.04 34.3,73.56 34.34,73.6 34.82,73.6 35.2,73.22 35.2,73.06 35.71,72.56 35.71,71.89 35.69,71.87
PWR_1D0V_LX on BOTTOM: 39.55,86.97 39.55,87.63 39.34,87.83 38.51,87.83 38.4,87.94 38.4,89.21 38.48,89.28 40.72,89.28 40.72,88.11 40.69,88.09 40.28,88.09 39.85,87.66 39.85,86.97
PWR_1D8V_PH on BOTTOM: 104.04,94.06 103.33,94.77 103.33,97.06 103.35,97.08 104.47,97.08 104.93,96.62 105.97,96.62 105.99,96.6 105.99,96.34 105.97,96.32 105.18,96.32 105.08,96.22 105.08,94.24 104.9,94.06
PWR_1D8V_PVIN on BOTTOM: 110.67,95.28 110.46,95.48 108.15,95.48 108.05,95.58 108.05,96.01 107.75,96.32 107.09,96.32 107.06,96.34 107.06,96.65 108.56,96.65 109.17,97.26 111,97.26 111.35,96.9 111.35,95.4 111.23,95.28 ; 4 cut-outs
PWR_3D3V on BOTTOM: 27.18,26.11 27.18,31.07 29.31,33.2 33.38,33.2 33.55,33.02 33.55,27.64 32.05,26.14 31.8,26.14 31.78,26.11 ; 2 cut-outs
PWR_3D3V_HG on BOTTOM: 24.56,25.05 24.41,25.2 24.41,26.29 24.51,26.39 25.27,26.39 25.32,26.34 25.32,25.07 25.3,25.05
PWR_3D3V_LG on BOTTOM: 21.44,24.08 21.34,24.18 21.34,25.2 21.46,25.33 22.23,25.33 22.33,25.22 22.33,24.23 22.17,24.08
PWR_3D3V_PH on BOTTOM: 12.06,15.04 11.89,15.22 11.89,15.9 12.14,16.16 13.84,16.16 13.94,16.05 13.94,15.39 13.87,15.32 13.21,15.32 12.93,15.04 ; 1 cut-out
PWR_3D3V_PH on BOTTOM: 27.13,20.86 26.44,21.54 22.73,21.54 22.73,24.97 25.53,24.97 25.53,26.62 24.64,26.62 24.51,26.75 24.51,28.27 26.54,28.27 26.89,27.93 26.89,25.95 26.85,25.91 26.85,25.5 28.4,23.95 30.38,23.95 30.76,23.57 30.76,21.01 30.61,20.86
PWR_5V on TOP: 30.66,15.39 29.95,16.11 29.95,19.51 30.61,20.17 32.48,20.17 32.72,20.41 32.72,21.06 32.82,21.16 37.39,21.16 37.49,21.06 37.49,20.27 37.49,20.27 37.49,18.27 34.62,15.39 ; 1 cut-out
PWR_5V on BOTTOM: 30.58,15.42 30,16 30,19.53 31.62,21.16 36.98,21.16 37.45,20.69 37.45,16.76 36.11,15.42
PWR_5V_HG on BOTTOM: 13.67,10.67 13.39,10.95 13.39,11.53 13.41,11.56 14.45,11.56 14.58,11.43 14.58,10.75 14.5,10.67
PWR_5V_HG on BOTTOM: 25.5,12.27 25.41,12.36 25.41,12.48 25.09,12.79 24.92,12.79 24.91,12.79 24.74,12.79 24.59,12.95 24.59,14.23 25.31,14.23 25.49,14.4 26.02,14.4 26.14,14.29 26.14,13.58 26.15,13.57 26.15,12.46 25.96,12.27
PWR_5V_LG on BOTTOM: 21.59,19.51 21.46,19.64 21.46,20.78 21.59,20.91 22.23,20.91 22.35,20.78 22.35,19.76 22.1,19.51
PWR_5V_PH on BOTTOM: 16.26,7.43 14.88,8.82 12.9,8.82 12.6,9.12 12.6,9.6 12.85,9.86 15.16,9.86 16.38,8.64 16.38,8.64 16.55,8.46 18.99,8.46 19.05,8.4 19.05,7.51 18.98,7.43
PWR_5V_PH on BOTTOM: 26.42,13.67 26.29,13.79 26.29,14.3 26.04,14.56 24.51,14.56 24.51,16.97 24.38,17.1 22.99,17.1 22.86,17.22 22.86,20.4 22.99,20.52 27.58,20.52 28.4,19.71 28.4,16.26 28.45,16.21 28.45,13.92 28.19,13.67
PWR_CHG_HIDRV on BOTTOM: 135.15,17.76 135.08,17.83 135.08,18.95 135.23,19.1 136.3,19.1 136.3,18.42 136.09,18.42 135.99,18.32 135.99,17.88 135.86,17.76
PWR_CHG_LODRV on BOTTOM: 141.63,21.44 141.6,21.46 141.6,22.23 141.55,22.28 141.55,22.96 141.83,23.24 142.42,23.24 142.6,23.06 142.6,21.67 142.37,21.44
PWR_CHG_PHASE on BOTTOM: 136.6,28.55 136.58,28.58 136.58,29.64 137.13,30.2 137.59,30.2 137.79,30 137.79,28.63 137.72,28.55
PWR_CHG_PHASE on BOTTOM: 135.84,15.32 135.23,15.93 135.23,17.45 135.38,17.6 135.99,17.6 136.14,17.76 136.14,18.06 136.53,18.44 136.53,19.13 138.68,19.13 139.06,19.51 139.06,20.91 142.52,20.91 142.54,20.88 142.54,17.65 140.21,15.32
PWR_CORE_BOOT1 on TOP: 32.66,47.96 31.57,49.05 31.57,49.56 32.23,49.56 32.23,49.33 32.59,48.97 33.4,48.97 33.46,49.03 34.42,49.03 34.52,48.94 34.52,48.02 34.46,47.96
PWR_CORE_BOOT_1 on TOP: 35.08,48 35.02,48.07 35.02,49.19 34.92,49.29 34.48,49.29 34.46,49.3 34.46,49.69 34.51,49.74 35.15,49.74 35.32,49.9 36.17,49.9 36.32,49.75 36.32,48.18 36.15,48 ; 1 cut-out
PWR_CORE_PH1 on BOTTOM: 41.81,39.19 41.76,39.24 41.76,44.55 41.91,44.71 41.91,47.32 41.4,47.83 36.32,47.83 36.2,47.96 36.2,50.62 36.32,50.75 44.07,50.75 44.65,50.17 44.65,39.27 44.58,39.19
PWR_DCBATOUT_0D95V on BOTTOM: 41.4,70.94 41.26,71.08 36.2,71.08 35.92,71.36 35.92,72.73 34.9,73.75 34.66,73.75 34.54,73.86 33.02,73.86 33.02,75.01 34.54,75.01 34.67,75.13 35.43,75.13 36.96,73.61 41.91,73.61 43.74,71.78 43.74,71.02 43.68,70.96 43.19,70.96 43.18,70.94
PWR_DCBATOUT_3D3V on BOTTOM: 17.78,25.5 17.78,26.95 17.37,27.36 17.37,28.11 17.59,28.32 18.41,28.32 18.87,28.78 23.88,28.78 23.95,28.7 23.95,25.53 23.93,25.5 ; 2 cut-outs
PWR_DCBATOUT_5V on BOTTOM: 18.16,13.41 17.91,13.67 17.91,16.59 18.29,16.97 19.3,16.97 19.43,16.84 23.75,16.84 24,16.59 24,13.54 23.88,13.41 ; 2 cut-outs
PWR_DCBATOUT_VCCCORE on TOP: 36.04,41.94 35.92,42.06 35.92,44.81 36.12,45.01 39.4,45.01 40.16,44.25 40.16,42.32 39.78,41.94 ; 3 cut-outs
PWR_DCBATOUT_VCCCORE on BOTTOM: 40.39,39.32 40.39,40.59 40.13,40.84 33.4,40.84 33.4,46.31 33.83,46.74 35.56,46.74 36.27,47.45 41.27,47.45 41.4,47.32 41.4,46.56 40.26,46.56 39.75,46.05 39.75,45.16 40.26,44.65 41.15,44.65 41.27,44.53 41.27,39.32
PWR_DCBATOUT_VDDNB on TOP: 34.85,60.73 34.77,60.81 34.77,62.99 35.64,63.86 38.84,63.86 39.07,63.63 39.07,62.56 38.94,62.43 35.97,62.43 35.71,62.18 35.71,60.96 35.48,60.73 ; 3 cut-outs
PWR_DCBATOUT_VDDNB on BOTTOM: 34.92,58.88 34.42,59.39 34.42,62.56 34.67,62.82 34.67,66.37 38.73,66.37 39.62,67.26 41.4,67.26 41.4,58.88
PWR_DCBATOUT_VDDQ on BOTTOM: 138.05,45.9 138.05,47.4 137.79,47.65 137.79,48.92 140.26,51.39 140.26,51.89 140.46,52.1 142.04,52.1 142.14,52 142.14,51.69 142.28,51.55 144.51,51.55 144.55,51.51 144.55,50.27 144.35,50.07 143.92,50.07 143.38,49.53 142.09,49.53 141.74,49.19 140.91,49.19 139.22,47.5 139.22,45.95 139.17,45.9 ; 1 cut-out
PWR_VDDNB_PH on BOTTOM: 36.02,55.5 35.97,55.55 35.97,58.47 35.99,58.5 41.66,58.5 41.66,61.77 41.86,61.98 41.86,67.18 41.88,67.21 44.75,67.21 44.75,55.75 44.5,55.5
PWR_VDDQ on TOP: 134.87,55.07 133.73,56.21 133.73,62.05 138.18,62.05 138.56,61.67 138.56,55.32 138.3,55.07
PWR_VDDQ on BOTTOM: 134.19,54.99 133.5,55.68 133.5,61.27 133.86,61.62 138.86,61.62 138.96,61.52 138.96,55.7 138.25,54.99 ; 8 cut-outs
PWR_VDDQ_PH on BOTTOM: 136.3,44.48 136.25,44.53 136.25,47.68 134.85,49.07 134.85,52.99 134.98,53.11 137.95,53.11 138.51,52.55 138.51,49.94 137.64,49.07 137.64,47.5 137.79,47.35 137.79,44.53 137.74,44.48
PWR_VDDQ_VTT on BOTTOM: 140.21,40.51 140.21,44.6 139.95,44.86 139.42,44.86 139.42,45.06 140.11,45.06 140.44,44.73 140.84,44.73 141.11,44.46 141.11,43.91 141.39,43.63 141.39,41.34 141.76,40.97 141.76,40.54 141.73,40.51 ; 2 cut-outs
RING2 on TOP: 146.81,92.46 146.81,93.32 146.79,93.35 146.79,94.03 146.94,94.18 147.24,94.18 147.45,93.98 147.45,93.63 147.04,93.22 147.04,92.46
RING2 on TOP: 148.29,94.87 148.18,94.97 148.18,95.45 148.3,95.57 148.3,96.43 148.36,96.5 148.97,96.5 149.56,97.08 149.56,97.21 149.68,97.33 150.09,97.33 150.22,97.21 150.22,96.01 149.83,95.63 149.05,95.63 148.87,95.45 148.87,94.95 148.79,94.87
RING2_R on TOP: 148.34,96.98 148.31,97 148.31,98.68 148.51,98.88 149.15,98.88 149.35,98.68 149.35,97 149.33,96.98
RING2_R on BOTTOM: 136.5,94.89 135.92,95.48 135.92,96.37 136.27,96.72 137.77,96.72 137.85,96.65 137.85,95.38 137.84,95.38 137.84,94.91 137.82,94.89
SD1_POWER on L3: 50.01,86.9 50.01,86.08 50.06,86.03 51.54,86.03 53.26,87.76 54.46,87.76 56.92,90.22 56.92,90.71 57.25,91.04 57.78,91.04 58.14,91.39 58.14,92.05 58.06,92.13 56.82,92.13 55.63,90.93 55.63,90.12 54.1,88.6 51.71,88.6
SLEEVE on TOP: 146.43,92.48 146.43,93.25 146.38,93.3 146.38,94.52 146.53,94.67 146.94,94.67 147.09,94.82 147.09,95.35 146.91,95.53 146.91,96.47 147.04,96.6 147.88,96.6 148.11,96.37 148.11,95.76 147.98,95.63 147.98,94.82 148.06,94.74 148.79,94.74 148.82,94.72 148.82,94.26 148.81,94.25 147.46,94.25 147.35,94.36 146.89,94.36 146.63,94.11 146.63,92.51 146.61,92.48 ; 2 cut-outs
SLEEVE_R on TOP: 147.07,97 147.04,97.03 147.04,98.76 147.19,98.91 147.85,98.91 148.03,98.73 148.03,97
SLEEVE_R on BOTTOM: 136.74,92.88 136.71,92.92 136.71,93.09 134.47,95.33 134.47,95.71 134.75,95.99 135.25,95.99 136.54,94.71 137.84,94.71 137.9,94.65 137.9,92.93 137.85,92.88
TP_VDD on TOP: 40.42,13.08 40.23,13.27 40.23,14.3 40.26,14.34 41.37,14.34 41.38,14.33 41.38,13.36 41.1,13.08
TP_VDD_1D8V on BOTTOM: 42.19,16.56 41.94,16.81 41.94,17.68 41.96,17.7 43.06,17.7 43.09,17.67 43.09,16.94 42.71,16.56
VPP_2D5V on TOP: 119.94,84.28 116.64,87.58 116.64,88.19 116.79,88.34 118.49,88.34 119.66,87.17 120.68,87.17 121.41,86.44 122.43,86.44 122.61,86.62 123.49,86.62 123.83,86.29 123.83,84.89 123.72,84.79 123.37,84.79 122.86,84.28 ; 3 cut-outs
VPP_2D5V on BOTTOM: 116.51,87.53 116.46,87.58 116.46,91.14 119.56,94.24 126.09,94.24 126.29,94.03 126.29,93.04 126.19,92.94 120.02,92.94 117.78,90.71 117.78,87.78 117.53,87.53
VPP_IN on BOTTOM: 115.04,93.3 114.76,93.58 114.76,95.18 114.78,95.2 115.75,95.2 115.75,95.05 116.18,94.62 117.2,94.62 117.25,94.67 117.25,95.02 117.37,95.15 118.98,95.15 119.13,95.3 119.13,98.48 119.18,98.53 122.1,98.53 122.15,98.48 122.15,94.9 121.77,94.52 119.53,94.52 118.31,93.3 ; 2 cut-outs
VPP_PWR on BOTTOM: 122.43,94.49 122.4,94.52 122.4,96.39 122.43,96.42 124,96.42 124.54,96.95 124.54,97.66 124.74,97.87 126.61,97.87 126.73,97.75 126.73,97.18 126.68,97.13 125.65,97.13 125.45,96.93 125.45,95.99 125.6,95.84 125.93,95.84 126.14,95.63 126.14,94.74 125.88,94.49 ; 2 cut-outs

Small or netless copper shapes (teardrops, artwork), in the pictures only: 1 on TOP, 1 on BOTTOM

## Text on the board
Ref Des/Silkscreen Bottom: Big Head | X1601:48MHZ | X1701:32.768KHZ | F5701:1.1A/6V | F5503:1.1A/6V | F5502:1.1A/6V | F5501:1.1A/24V | WLAN
User.Comments: CR_1.8_1 | CR_CPU_1
Ref Des/Silkscreen Top: X6301:30MHZ | Rocket 11 MLK AMD | 17876-1 | CY5JK | MADE IN TAIWAN
User.31: ByImpedance:100.0@_REF_L2=("4.0/5.5(L3)")|_REF_L1=("5.0/4.0(L3)")|_REF_L6=("5.0/4.0(L4)")|Type="DP"|_REF_L4=("3.5/4.5(L2/L5)")|_REF_L3=("3.5/4.5(L2/L5)")|imp="100.0" | ByImpedance:40.0@_REF_L2=("3.5(L1/L3)" "10.0(L3)")|_REF_L1=("5.5(L2)")|_REF_L6=("5.5(L5)")|Type="SE"|_REF_L4=("8.51(L3/L5)" "8.5(L2/L5)")|_REF_L3=("8.5(L2/L5)")|imp="40.0" | ByImpedance:45.0@_REF_L2=("8.0(L3)")|_REF_L1=("4.5(L2)")|_REF_L6=("4.5(L5)")|Type="SE"|_REF_L4=("7.0(L2/L5)")|_REF_L3=("7.0(L2/L5)")|imp="45.0" | ByImpedance:48.0@_REF_L2=("7.0(L3)")|_REF_L1=("4.0(L2)")|_REF_L6=("4.0(L5)")|Type="SE"|_REF_L4=("6.0(L2/L5)")|_REF_L3=("6.0(L2/L5)")|imp="48.0" | ByImpedance:50.0@_REF_L2=("6.5(L3)")|_REF_L1=("3.5(L2)")|_REF_L6=("3.5(L5)")|Type="SE"|_REF_L4=("5.5(L2/L5)" "5.51(L3/L5)")|_REF_L3=("5.5(L2/L5)")|imp="50.0" | ByImpedance:52.0@_REF_L2=("6.0(L3)")|_REF_L1=("3.0(L2)")|_REF_L6=("3.0(L5)")|Type="SE"|_REF_L4=("5.0(L2/L5)")|_REF_L3=("5.0(L2/L5)")|imp="52.0" | ByImpedance:55.0@_REF_L2=("5.0(L3)")|Type="SE"|_REF_L4=("4.5(L2/L5)")|_REF_L3=("4.5(L2/L5)")|imp="55.0" | ByImpedance:72.0@_REF_L2=("8.0/4.0(L3)")|_REF_L1=("5.5/5.0(L2)")|_REF_L6=("5.5/5.0(L5)")|Type="DP"|_REF_L4=("7.5/4.0(L2/L5)")|_REF_L3=("7.5/4.0(L2/L5)")|imp="72.0" | ByImpedance:80.0@_REF_L2=("6.0/4.0(L3)")|_REF_L1=("4.5/5.0(L2)")|_REF_L6=("4.5/5.0(L5)")|Type="DP"|_REF_L4=("6.0/4.0(L2/L5)")|_REF_L3=("6.0/4.0(L2/L5)")|imp="80.0" | ByImpedance:83.0@_REF_L2=("5.5/4.0(L3)")|_REF_L1=("4.0/5.0(L2)")|_REF_L6=("4.0/5.0(L5)")|Type="DP"|_REF_L4=("5.51/4.0(L3/L5)" "5.5/4.0(L2/L5)")|_REF_L3=("5.5/4.0(L2/L5)")|imp="83.0" | ByImpedance:85.0@_REF_L2=("5.0/4.0(L3)")|_REF_L1=("3.5/4.5(L2)")|_REF_L6=("3.5/4.5(L5)")|Type="DP"|_REF_L4=("5.0/4.0(L2/L5)" "5.1/4.0(L3/L5)")|_REF_L3=("5.0/4.0(L2/L5)")|imp="85.0" | ByImpedance:90.0@_REF_L2=("5.0/5.0(L3)")|_REF_L1=("3.5/6.0(L2)")|_REF_L6=("3.5/6.0(L5)")|Type="DP"|_REF_L4=("4.5/4.0(L2/L5)")|_REF_L3=("4.5/4.0(L2/L5)")|imp="90.0" | LayerIndex:nil | Source:6-1.0-8d.xls | artWorks:("_REF_L3" "_REF_L4" "_REF_L2" "_REF_L6" "_REF_L1") | gtImpOutlineUsed:BOARD GEOMETRY/PANEL_OUTLINE
User.34: Board Accuracy Check,Dec 13 17:01:20 2017,Passed | Dummy-Static-No Shape On Layer Check,Dec 13 17:01:20 2017,Passed | Split Plane Check,Aug 22 15:32:16 2017,Passed
User.35: GND | AUD_AGND
User.36: 5V_S5 | 3D3V_S5 | 3D3V_S0 | 5V_S0 | 0D95V_S5 | GND | 1D2V_CPU_VDDNB | 0D95V_S0 | 1V_CPU_CORE | 1D2V_S3 | AUD_AGND
User.42: This gerber is just for your reference to find the DP impedance traces in layer L1. | DP IMPEDANCE TABLE: L1 | * - Denotes that this Impedance | is NOT used | IMP(Ohm) | *72.0 | *80.0 | *83.0 | 85.0 | 90.0 | *100.0 | WIDTH(mils) | 5.5/5.0 | 4.5/5.0 | 4.0/5.0 | 3.5/4.5 | 3.5/6.0 | 5.0/4.0 | TYPE | DP | Ref. Plane | L2 | L3
User.44: This gerber is just for your reference to find the SE impedance traces in layer L1. | SE IMPEDANCE TABLE: L1 | * - Denotes that this Impedance | is NOT used | IMP(Ohm) | 40.0 | *45.0 | *48.0 | 50.0 | *52.0 | WIDTH(mils) | 5.5 | 4.5 | 4.0 | 3.5 | 3.0 | TYPE | SE | Ref. Plane | L2
User.45: Note:Refer to DRILL layer for ELLIPSE drill direction | FIGURE | SIZE | 8.0 | 10.0 | 12.0 | 16.0 | 20.0 | 28.0 | 30.0 | 142.0 | 178.0 | 197.0 | 237.0 | 44.0 | 46.0 | 63.0 | 65.0 | 86.0 | 119.0 | 157.0 | 36.0x18.0 | 56.0x36.0 | 71.0x32.0 | 79.0x32.0 | 82.0x40.0 | 97.0x36.0 | DRILL CHART: TOP to BOTTOM | ALL UNITS ARE IN MILS | PLATED | NON-PLATED | QTY | 14 | 2382 | 2 | 480 | 19 | 9 | 22 | 1 | 4 | 6 | This gerber is just for your reference to find the DP impedance traces in layer L2. | This gerber is just for your reference to find the DP impedance traces in layer L3. | This gerber is just for your reference to find the DP impedance traces in layer L4. | This gerber is just for your reference to find the DP impedance traces in layer L6. | This gerber is just for your reference to find the SE impedance traces in layer L2. | This gerber is just for your reference to find the SE impedance traces in layer L3. | This gerber is just for your reference to find the SE impedance traces in layer L4. | This gerber is just for your reference to find the SE impedance traces in layer L6. | DP IMPEDANCE TABLE: L2 | DP IMPEDANCE TABLE: L3 | DP IMPEDANCE TABLE: L4 | DP IMPEDANCE TABLE: L6 | SE IMPEDANCE TABLE: L2 | SE IMPEDANCE TABLE: L3 | SE IMPEDANCE TABLE: L4 | SE IMPEDANCE TABLE: L6 | * - Denotes that this Impedance | is NOT used | Model | Rocket 11 MLK AMD | PCB_NO | 17876 | VER. | Layer | DRILL | L1 | L2VCC | L3 | TMASK | TPLACE | TSILK | TSMD | Designer | REN | IMP(Ohm) | *40.0 | *72.0 | 40.0 | 72.0 | *45.0 | *80.0 | 80.0 | *48.0 | *83.0 | *85.0 | 50.0 | 85.0 | *50.0 | *52.0 | *90.0 | 90.0 | *100.0 | *55.0 | Date | 12/13/2017 | WIDTH(mils) | 3.5 | 5.5 | 8.5 | 4.5 | 7.0 | 4.0 | 6.0 | 3.0 | 5.0 | 6.5 | 5.5/5.0 | 8.0/4.0 | 8.51 | 4.5/5.0 | 6.0/4.0 | 4.0/5.0 | 5.5/4.0 | 3.5/4.5 | 5.0/4.0 | 3.5/6.0 | 5.0/5.0 | 4.0/5.5 | 5.51 | 7.5/4.0 | 4.5/4.0 | 5.51/4.0 | 5.1/4.0 | TYPE | SE | DP | Ref. Plane | L1/L3 | L2/L5 | L5 | L3/L5 | L4 | BMASK | BPLACE | BSILK | BSMD | L5GND | L6
